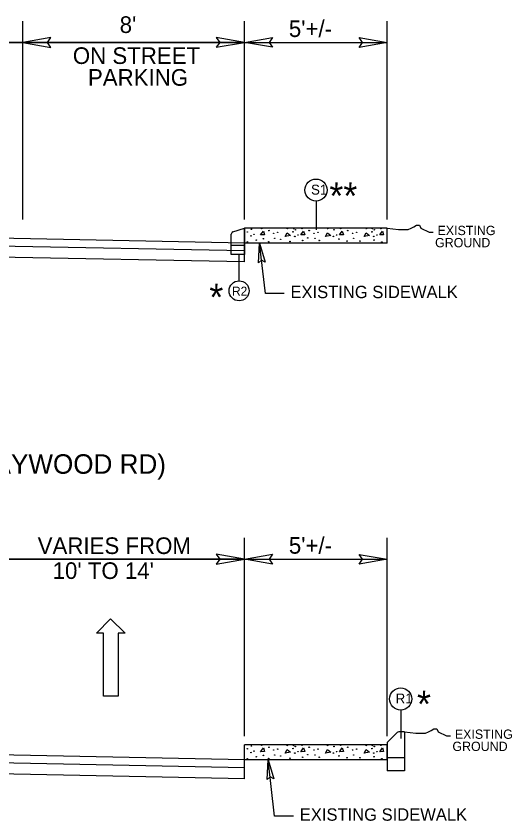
# Model space of a CAD drawing. Extents: x 1022283 to 1026986, y 174822 to 180471.
# Drawn here: x 1024096 to 1024572, y 178949 to 179724 of the extents above; entities that cross this region are included whole.
import ezdxf

# ---------------------------------------------------------------- set-up
doc = ezdxf.new("R2010")
doc.units = 0
for name, color, linetype in [('Default', 7, 'Continuous'), ('Prop Dimension', 7, 'Continuous'), ('Prop Lane Arrow CELL', 7, 'Continuous'), ('Prop Terminator CELL', 7, 'Continuous'), ('Typical Curb CELL', 7, 'Continuous'), ('Typical ID Circle CELL', 7, 'Continuous'), ('Typical Slope Point Local CELL', 7, 'Continuous'), ('Typical Text General CELL', 7, 'Continuous'), ('Typical Text ID Circle CELL', 7, 'Continuous')]:
    doc.layers.add(name, color=color, linetype=linetype)

# ---------------------------------------------------------------- blocks, each defined once
blk = doc.blocks.new('Terminator')
at = {"layer": 'Prop Terminator CELL'}
blk.add_lwpolyline([(-9, 1.55), (0, 0), (-9.05, -1.6), (-7.9, 0)], close=True, dxfattribs=at)
blk = doc.blocks.new('Lane Arrow Through')
at = {"layer": 'Prop Lane Arrow CELL'}
for p, q in [((-3.15, 1.6), (-3.15, 3.1)), ((-3.15, 3.1), (0, 0)), ((-17.15, 1.6), (-3.15, 1.6)), ((-17.15, -1.7), (-17.15, 1.6)), ((0, 0), (-3.15, -3.2)), ((-3.15, -1.7), (-17.15, -1.7)), ((-3.15, -3.2), (-3.15, -1.7))]:
    blk.add_line(p, q, dxfattribs=at)

msp = doc.modelspace()

# ---------------------------------------------------------------- linework, layer by layer
at = {"layer": 'Default'}
for p, q in [((1024102.03, 179527.88), (1024102.03, 179718.7)), ((1024315.21, 179527.88), (1024315.21, 179718.7)), ((1024452.59, 179527.88), (1024452.59, 179718.7)), ((1023807.5, 179698.14), (1024315.21, 179698.14)), ((1024315.21, 179698.14), (1023807.5, 179698.14)), ((1024315.21, 179698.14), (1024452.59, 179698.14)), ((1024315.21, 179030.88), (1024315.21, 179221.7)), ((1024452.59, 179030.88), (1024452.59, 179221.7)), ((1023807.5, 179201.13), (1024315.21, 179201.13)), ((1024315.21, 179201.13), (1023807.5, 179201.13)), ((1024315.21, 179201.13), (1024452.59, 179201.13))]:
    msp.add_line(p, q, dxfattribs=at)
at = {"layer": 'Prop Dimension'}
for p, q in [((1024315.21, 179505.09), (1023807.5, 179515.24)), ((1024315.21, 179505.09), (1023807.5, 179515.24)), ((1024315.21, 179497.58), (1023807.5, 179507.74)), ((1024315.21, 179497.58), (1023807.5, 179507.74)), ((1024335.36, 179456.63), (1024329.76, 179505.09)), ((1024315.21, 179487), (1023807.5, 179497.16)), ((1024353.51, 179456.63), (1024335.36, 179456.63)), ((1024315.21, 179008.08), (1023807.5, 179018.24)), ((1024315.21, 179008.08), (1023807.5, 179018.24)), ((1024315.21, 179000.58), (1023807.5, 179010.74)), ((1024315.21, 179000.58), (1023807.5, 179010.74)), ((1024344.3, 178954), (1024338.05, 179008.08)), ((1024315.21, 178990), (1023807.5, 179000.15)), ((1024362.45, 178954), (1024344.3, 178954))]:
    msp.add_line(p, q, dxfattribs=at)
at = {"layer": 'Prop Terminator CELL'}
for points in [[(1024129.03, 179702.79), (1024102.03, 179698.14), (1024129.18, 179693.34), (1024125.73, 179698.14)], [(1024288.21, 179693.49), (1024315.21, 179698.14), (1024288.06, 179702.94), (1024291.51, 179698.14)], [(1024342.21, 179693.49), (1024315.21, 179698.14), (1024342.36, 179702.94), (1024338.91, 179698.14)], [(1024425.59, 179702.79), (1024452.59, 179698.14), (1024425.44, 179693.34), (1024428.89, 179698.14)], [(1024288.21, 179196.48), (1024315.21, 179201.13), (1024288.06, 179205.93), (1024291.51, 179201.13)], [(1024342.21, 179196.48), (1024315.21, 179201.13), (1024342.36, 179205.93), (1024338.91, 179201.13)], [(1024425.59, 179205.78), (1024452.59, 179201.13), (1024425.44, 179196.33), (1024428.89, 179201.13)]]:
    msp.add_lwpolyline(points, close=True, dxfattribs=at)
at = {"layer": 'Typical Curb CELL'}
for p, q in [((1024304.24, 179515.95), (1024315.21, 179519.61)), ((1024315.21, 179488.61), (1024315.21, 179519.61)), ((1024315.21, 179509.27), (1024315.21, 179519.61)), ((1024315.21, 179509.27), (1024315.21, 179519.61)), ((1024452.59, 179519.61), (1024315.21, 179519.61)), ((1024315.21, 179487), (1024315.21, 179519.61)), ((1024315.21, 179488.61), (1024315.21, 179519.61)), ((1024315.21, 179509.27), (1024315.21, 179519.61)), ((1024315.21, 179509.27), (1024315.21, 179519.61)), ((1024452.59, 179519.61), (1024315.21, 179519.61)), ((1024315.21, 179487), (1024315.21, 179519.61)), ((1024315.21, 179488.61), (1024315.21, 179519.61)), ((1024315.21, 179509.27), (1024315.21, 179519.61)), ((1024315.21, 179509.27), (1024315.21, 179519.61)), ((1024315.21, 179487), (1024315.21, 179519.61)), ((1024315.21, 179488.61), (1024315.21, 179519.61)), ((1024315.21, 179509.27), (1024315.21, 179519.61)), ((1024315.21, 179509.27), (1024315.21, 179519.61)), ((1024315.21, 179487), (1024315.21, 179519.61)), ((1024315.21, 179519.61), (1024315.21, 179502.74)), ((1024330.79, 179512.98), (1024333.47, 179516.7)), ((1024330.79, 179512.98), (1024333.47, 179516.7)), ((1024333.47, 179516.7), (1024334.54, 179513.18)), ((1024333.47, 179516.7), (1024334.54, 179513.18)), ((1024369.55, 179512.98), (1024372.19, 179516.7)), ((1024369.55, 179512.98), (1024372.19, 179516.7)), ((1024372.19, 179516.7), (1024373.26, 179513.18)), ((1024372.19, 179516.7), (1024373.26, 179513.18)), ((1024406.68, 179512.98), (1024409.36, 179516.7)), ((1024406.68, 179512.98), (1024409.36, 179516.7)), ((1024409.36, 179516.7), (1024410.43, 179513.18)), ((1024409.36, 179516.7), (1024410.43, 179513.18)), ((1024445.44, 179512.98), (1024448.08, 179516.7)), ((1024445.44, 179512.98), (1024448.08, 179516.7)), ((1024448.08, 179516.7), (1024449.15, 179513.18)), ((1024448.08, 179516.7), (1024449.15, 179513.18)), ((1024452.59, 179505.09), (1024452.59, 179519.61)), ((1024452.59, 179505.09), (1024452.59, 179519.61)), ((1024302.56, 179502.74), (1024302.56, 179513.62)), ((1024334.54, 179513.18), (1024330.79, 179512.98)), ((1024334.54, 179513.18), (1024330.79, 179512.98)), ((1024354.53, 179511.4), (1024356.47, 179514.95)), ((1024354.53, 179511.4), (1024356.47, 179514.95)), ((1024359.66, 179512.63), (1024354.53, 179511.4)), ((1024359.66, 179512.63), (1024354.53, 179511.4)), ((1024356.47, 179514.95), (1024359.66, 179512.63)), ((1024356.47, 179514.95), (1024359.66, 179512.63)), ((1024373.26, 179513.18), (1024369.55, 179512.98)), ((1024373.26, 179513.18), (1024369.55, 179512.98)), ((1024393.25, 179511.4), (1024395.19, 179514.95)), ((1024393.25, 179511.4), (1024395.19, 179514.95)), ((1024398.39, 179512.63), (1024393.25, 179511.4)), ((1024398.39, 179512.63), (1024393.25, 179511.4)), ((1024395.19, 179514.95), (1024398.39, 179512.63)), ((1024395.19, 179514.95), (1024398.39, 179512.63)), ((1024410.43, 179513.18), (1024406.68, 179512.98)), ((1024410.43, 179513.18), (1024406.68, 179512.98)), ((1024430.42, 179511.4), (1024432.36, 179514.95)), ((1024430.42, 179511.4), (1024432.36, 179514.95)), ((1024435.55, 179512.63), (1024430.42, 179511.4)), ((1024435.55, 179512.63), (1024430.42, 179511.4)), ((1024432.36, 179514.95), (1024435.55, 179512.63)), ((1024432.36, 179514.95), (1024435.55, 179512.63)), ((1024449.15, 179513.18), (1024445.44, 179512.98)), ((1024449.15, 179513.18), (1024445.44, 179512.98)), ((1024315.21, 179502.74), (1024302.56, 179502.74)), ((1024302.56, 179494.3), (1024302.56, 179502.74)), ((1024452.59, 179505.09), (1024315.21, 179505.09)), ((1024315.21, 179502.74), (1024315.21, 179494.3)), ((1024315.21, 179494.3), (1024302.56, 179494.3)), ((1024452.59, 179024.69), (1024461.42, 179033.84)), ((1024469.25, 179035.11), (1024464.42, 179035.11)), ((1024469.25, 179035.11), (1024469.25, 179010.11)), ((1024315.21, 178991.6), (1024315.21, 179022.61)), ((1024315.21, 179012.27), (1024315.21, 179022.61)), ((1024315.21, 179012.27), (1024315.21, 179022.61)), ((1024452.59, 179022.61), (1024315.21, 179022.61)), ((1024315.21, 178990), (1024315.21, 179022.61)), ((1024315.21, 178991.6), (1024315.21, 179022.61)), ((1024315.21, 179012.27), (1024315.21, 179022.61)), ((1024315.21, 179012.27), (1024315.21, 179022.61)), ((1024452.59, 179022.61), (1024315.21, 179022.61)), ((1024315.21, 178990), (1024315.21, 179022.61)), ((1024452.59, 179024.69), (1024452.59, 179010.11)), ((1024452.59, 179008.08), (1024452.59, 179022.61)), ((1024452.59, 179008.08), (1024452.59, 179022.61)), ((1024330.79, 179015.98), (1024333.47, 179019.69)), ((1024330.79, 179015.98), (1024333.47, 179019.69)), ((1024334.54, 179016.17), (1024330.79, 179015.98)), ((1024334.54, 179016.17), (1024330.79, 179015.98)), ((1024333.47, 179019.69), (1024334.54, 179016.17)), ((1024333.47, 179019.69), (1024334.54, 179016.17)), ((1024354.53, 179014.4), (1024356.47, 179017.95)), ((1024354.53, 179014.4), (1024356.47, 179017.95)), ((1024359.66, 179015.62), (1024354.53, 179014.4)), ((1024359.66, 179015.62), (1024354.53, 179014.4)), ((1024356.47, 179017.95), (1024359.66, 179015.62)), ((1024356.47, 179017.95), (1024359.66, 179015.62)), ((1024369.55, 179015.98), (1024372.19, 179019.69)), ((1024369.55, 179015.98), (1024372.19, 179019.69)), ((1024373.26, 179016.17), (1024369.55, 179015.98)), ((1024373.26, 179016.17), (1024369.55, 179015.98)), ((1024372.19, 179019.69), (1024373.26, 179016.17)), ((1024372.19, 179019.69), (1024373.26, 179016.17)), ((1024393.25, 179014.4), (1024395.19, 179017.95)), ((1024393.25, 179014.4), (1024395.19, 179017.95)), ((1024398.39, 179015.62), (1024393.25, 179014.4)), ((1024398.39, 179015.62), (1024393.25, 179014.4)), ((1024395.19, 179017.95), (1024398.39, 179015.62)), ((1024395.19, 179017.95), (1024398.39, 179015.62)), ((1024406.68, 179015.98), (1024409.36, 179019.69)), ((1024406.68, 179015.98), (1024409.36, 179019.69)), ((1024410.43, 179016.17), (1024406.68, 179015.98)), ((1024410.43, 179016.17), (1024406.68, 179015.98)), ((1024409.36, 179019.69), (1024410.43, 179016.17)), ((1024409.36, 179019.69), (1024410.43, 179016.17)), ((1024430.42, 179014.4), (1024432.36, 179017.95)), ((1024430.42, 179014.4), (1024432.36, 179017.95)), ((1024435.55, 179015.62), (1024430.42, 179014.4)), ((1024435.55, 179015.62), (1024430.42, 179014.4)), ((1024432.36, 179017.95), (1024435.55, 179015.62)), ((1024432.36, 179017.95), (1024435.55, 179015.62)), ((1024445.44, 179015.98), (1024448.08, 179019.69)), ((1024445.44, 179015.98), (1024448.08, 179019.69)), ((1024449.15, 179016.17), (1024445.44, 179015.98)), ((1024449.15, 179016.17), (1024445.44, 179015.98)), ((1024448.08, 179019.69), (1024449.15, 179016.17)), ((1024448.08, 179019.69), (1024449.15, 179016.17)), ((1024452.59, 179008.08), (1024315.21, 179008.08)), ((1024452.59, 179010.24), (1024452.59, 178997.61)), ((1024469.25, 179010.11), (1024452.59, 179010.11)), ((1024469.25, 179010.24), (1024469.25, 178997.61)), ((1024469.25, 178997.61), (1024452.59, 178997.61))]:
    msp.add_line(p, q, dxfattribs=at)
for centre in [(1024318.07, 179515.81), (1024318.07, 179515.81), (1024322.01, 179518.49), (1024322.01, 179518.49), (1024331.87, 179519.19), (1024331.87, 179519.19), (1024338.77, 179517.25), (1024338.77, 179517.25), (1024347.27, 179515.47), (1024347.27, 179515.47), (1024356.47, 179519.01), (1024356.47, 179519.01), (1024361.96, 179516.01), (1024361.96, 179516.01), (1024362.49, 179519.01), (1024362.49, 179519.01), (1024364.23, 179517.95), (1024364.23, 179517.95), (1024370.6, 179519.19), (1024370.6, 179519.19), (1024377.51, 179517.25), (1024377.51, 179517.25), (1024386.01, 179515.47), (1024386.01, 179515.47), (1024395.21, 179519.01), (1024395.21, 179519.01), (1024401.38, 179517.95), (1024401.38, 179517.95), (1024407.76, 179519.19), (1024407.76, 179519.19), (1024414.66, 179517.25), (1024414.66, 179517.25), (1024423.16, 179515.47), (1024423.16, 179515.47), (1024432.36, 179519.01), (1024432.36, 179519.01), (1024437.85, 179516.01), (1024437.85, 179516.01), (1024438.38, 179519.01), (1024438.38, 179519.01), (1024440.12, 179517.95), (1024440.12, 179517.95), (1024446.49, 179519.19), (1024446.49, 179519.19), (1024321.52, 179512.11), (1024321.52, 179512.11), (1024324.5, 179513.53), (1024324.5, 179513.53), (1024326.67, 179508.05), (1024326.67, 179508.05), (1024333.51, 179509.34), (1024333.51, 179509.34), (1024343.38, 179514.59), (1024343.38, 179514.59), (1024344.43, 179509.81), (1024344.43, 179509.81), (1024350.05, 179508.76), (1024350.05, 179508.76), (1024363.73, 179511.58), (1024363.73, 179511.58), (1024366.71, 179513), (1024366.71, 179513), (1024371.23, 179507.66), (1024371.23, 179507.66), (1024376.21, 179510.18), (1024376.21, 179510.18), (1024382.11, 179514.59), (1024382.11, 179514.59), (1024383.17, 179509.81), (1024383.17, 179509.81), (1024387.19, 179507.66), (1024387.19, 179507.66), (1024400.89, 179511.58), (1024400.89, 179511.58), (1024403.87, 179513), (1024403.87, 179513), (1024406.11, 179508.96), (1024406.11, 179508.96), (1024419.27, 179514.59), (1024419.27, 179514.59), (1024420.32, 179509.81), (1024420.32, 179509.81), (1024439.62, 179511.58), (1024439.62, 179511.58), (1024439.96, 179508.05), (1024439.96, 179508.05), (1024442.6, 179513), (1024442.6, 179513), (1024318.07, 179506.31), (1024318.07, 179506.31), (1024338.62, 179506.44), (1024338.62, 179506.44), (1024359.03, 179506.69), (1024359.03, 179506.69), (1024414, 179507.08), (1024414, 179507.08), (1024426.27, 179507.08), (1024426.27, 179507.08), (1024447.39, 179506.11), (1024447.39, 179506.11), (1024322.01, 179021.49), (1024322.01, 179021.49), (1024331.87, 179022.19), (1024331.87, 179022.19), (1024338.77, 179020.24), (1024338.77, 179020.24), (1024356.47, 179022.01), (1024356.47, 179022.01), (1024362.49, 179022.01), (1024362.49, 179022.01), (1024364.23, 179020.95), (1024364.23, 179020.95), (1024370.6, 179022.19), (1024370.6, 179022.19), (1024377.51, 179020.24), (1024377.51, 179020.24), (1024395.21, 179022.01), (1024395.21, 179022.01), (1024401.38, 179020.95), (1024401.38, 179020.95), (1024407.76, 179022.19), (1024407.76, 179022.19), (1024414.66, 179020.24), (1024414.66, 179020.24), (1024432.36, 179022.01), (1024432.36, 179022.01), (1024438.38, 179022.01), (1024438.38, 179022.01), (1024440.12, 179020.95), (1024440.12, 179020.95), (1024446.49, 179022.19), (1024446.49, 179022.19), (1024318.07, 179018.8), (1024318.07, 179018.8), (1024321.52, 179015.11), (1024321.52, 179015.11), (1024324.5, 179016.53), (1024324.5, 179016.53), (1024333.51, 179012.34), (1024333.51, 179012.34), (1024343.38, 179017.59), (1024343.38, 179017.59), (1024344.43, 179012.81), (1024344.43, 179012.81), (1024347.27, 179018.47), (1024347.27, 179018.47), (1024350.05, 179011.76), (1024350.05, 179011.76), (1024361.96, 179019.01), (1024361.96, 179019.01), (1024363.73, 179014.58), (1024363.73, 179014.58), (1024366.71, 179015.99), (1024366.71, 179015.99), (1024376.21, 179013.18), (1024376.21, 179013.18), (1024382.11, 179017.59), (1024382.11, 179017.59), (1024383.17, 179012.81), (1024383.17, 179012.81), (1024386.01, 179018.47), (1024386.01, 179018.47), (1024400.89, 179014.58), (1024400.89, 179014.58), (1024403.87, 179015.99), (1024403.87, 179015.99), (1024406.11, 179011.95), (1024406.11, 179011.95), (1024419.27, 179017.59), (1024419.27, 179017.59), (1024420.32, 179012.81), (1024420.32, 179012.81), (1024423.16, 179018.47), (1024423.16, 179018.47), (1024437.85, 179019.01), (1024437.85, 179019.01), (1024439.62, 179014.58), (1024439.62, 179014.58), (1024442.6, 179015.99), (1024442.6, 179015.99), (1024318.07, 179009.3), (1024318.07, 179009.3), (1024326.67, 179011.05), (1024326.67, 179011.05), (1024338.62, 179009.43), (1024338.62, 179009.43), (1024359.03, 179009.69), (1024359.03, 179009.69), (1024371.23, 179010.66), (1024371.23, 179010.66), (1024387.19, 179010.66), (1024387.19, 179010.66), (1024414, 179010.08), (1024414, 179010.08), (1024426.27, 179010.08), (1024426.27, 179010.08), (1024439.96, 179011.05), (1024439.96, 179011.05), (1024447.39, 179009.11), (1024447.39, 179009.11)]:
    msp.add_circle(centre, 0.249, dxfattribs=at)
for centre, radius, start, end in [((1024305.02, 179513.62), 2.46, 108.43495, 180), ((1024464.42, 179030.94), 4.17, 90, 136.0003)]:
    msp.add_arc(centre, radius, start, end, dxfattribs=at)
at = {"layer": 'Typical ID Circle CELL'}
for p, q in [((1024384.1, 179545.46), (1024384.1, 179517.93)), ((1024310.13, 179468.83), (1024310.13, 179493.6)), ((1024465.55, 179056.04), (1024465.55, 179028.51))]:
    msp.add_line(p, q, dxfattribs=at)
for centre, radius in [((1024384.1, 179556.11), 10.65), ((1024310.13, 179459.24), 9.59), ((1024465.55, 179066.69), 10.65)]:
    msp.add_circle(centre, radius, dxfattribs=at)
at = {"layer": 'Typical Slope Point Local CELL'}
for points in [[(1024452.59, 179519.61), (1024463.36, 179518.27), (1024466.05, 179518.27), (1024470.1, 179518.27), (1024472.79, 179518.27), (1024475.48, 179519.61), (1024478.18, 179520.96), (1024480.87, 179522.32), (1024483.56, 179522.32), (1024484.91, 179519.61), (1024487.61, 179518.27), (1024490.3, 179516.92), (1024492.99, 179515.58), (1024495.69, 179515.58), (1024496.75, 179515.58)], [(1024452.59, 179519.61), (1024463.36, 179518.27), (1024466.05, 179518.27), (1024470.1, 179518.27), (1024472.79, 179518.27), (1024475.48, 179519.61), (1024478.18, 179520.96), (1024480.87, 179522.32), (1024483.56, 179522.32), (1024484.91, 179519.61), (1024487.61, 179518.27), (1024490.3, 179516.92), (1024492.99, 179515.58), (1024495.69, 179515.58), (1024496.75, 179515.58)], [(1024469.25, 179035.11), (1024480.03, 179033.77), (1024482.72, 179033.77), (1024486.76, 179033.77), (1024489.46, 179033.77), (1024492.15, 179035.11), (1024494.84, 179036.46), (1024497.54, 179037.81), (1024500.23, 179037.81), (1024501.58, 179035.11), (1024504.27, 179033.77), (1024506.97, 179032.42), (1024509.66, 179031.07), (1024512.35, 179031.07), (1024513.41, 179031.07)]]:
    msp.add_lwpolyline(points, dxfattribs=at)

# ---------------------------------------------------------------- block references
at = {"layer": 'Prop Dimension', "xscale": 2.0767499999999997, "yscale": 2.076749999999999, "rotation": 96.5883266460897}
for p in [(1024329.76, 179505.09), (1024338.05, 179008.08)]:
    msp.add_blockref('Terminator', p, dxfattribs=at)
at = {"layer": 'Prop Lane Arrow CELL', "xscale": 4.329849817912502, "yscale": 4.329849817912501, "rotation": 90.00000000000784}
msp.add_blockref('Lane Arrow Through', (1024186.56, 179143.7), dxfattribs=at)

# ---------------------------------------------------------------- texts
at = {"layer": 'Prop Dimension'}
for s, height, p in [("8'", 16, (1024195.3, 179707.27)), ("5'+/-", 16, (1024357.97, 179703.4)), ('ON STREET', 16, (1024150.23, 179677.47)), ('PARKING', 16, (1024164.76, 179656.5)), ('-EL- US 19/23 BUS (HAYWOOD RD) ', 18.75, (1023823.22, 179283.3)), ('VARIES FROM ', 16, (1024116.42, 179206.11)), ("5'+/-", 16, (1024357.97, 179206.4)), ("10' TO 14'", 16, (1024130.81, 179182.11))]:
    msp.add_text(s, height=height, dxfattribs=at).set_placement(p)
at = {"layer": 'Typical Slope Point Local CELL'}
for s, height, p in [('**', 25.771, (1024396.98, 179537.72)), ('EXISTING ', 8.938, (1024500.91, 179512.85)), ('EXISTING ', 8.938, (1024500.91, 179512.85)), ('GROUND', 8.938, (1024498.58, 179501.14)), ('GROUND', 8.938, (1024498.58, 179501.14)), ('*', 25.77, (1024281.53, 179440.31)), ('*', 25.77, (1024481.21, 179048.94)), ('EXISTING ', 8.938, (1024517.58, 179028.35)), ('GROUND', 8.938, (1024515.25, 179016.63))]:
    msp.add_text(s, height=height, dxfattribs=at).set_placement(p)
at = {"layer": 'Typical Text General CELL'}
for p in [(1024359.55, 179452.2), (1024368.49, 178949.57)]:
    msp.add_text('EXISTING SIDEWALK', height=11.8979, dxfattribs=at).set_placement(p)
at = {"layer": 'Typical Text ID Circle CELL'}
for s, height, p in [('S1', 9.534, (1024379.3, 179551.81)), ('R2', 8.581, (1024303.33, 179454.69)), ('R1', 9.534, (1024460.68, 179062.38))]:
    msp.add_text(s, height=height, dxfattribs=at).set_placement(p)

doc.saveas('drawing.dxf')
